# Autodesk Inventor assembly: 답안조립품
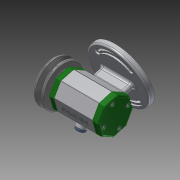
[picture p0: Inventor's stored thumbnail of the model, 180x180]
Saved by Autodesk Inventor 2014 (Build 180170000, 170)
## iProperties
Created: 2017-06
Part Number: 답안조립품
Document SubType Name: Assembly
Designer: Administrator
Author: Administrator
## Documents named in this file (13)
- C:\Users\Administrator\Desktop\470607V1004\답안조립품.iam
- C:\Users\Administrator\Desktop\470607V1004\축.ipt
- C:\Users\Administrator\Desktop\470607V1004\키 3 x 3 x 12.ipt
- C:\Users\Administrator\Desktop\470607V1004\베어링 15 x 32 x 9.ipt
- C:\Users\Administrator\Desktop\470607V1004\뒤커버.ipt
- C:\Users\Administrator\Desktop\470607V1004\본체.ipt
- C:\Users\Administrator\Desktop\470607V1004\앞커버.ipt
- C:\Users\Administrator\Desktop\470607V1004\볼트 M4 x 12.ipt
- C:\Users\Administrator\Desktop\470607V1004\V벨트풀리.ipt
- C:\Users\Administrator\Desktop\470607V1004\와셔 8x17.ipt
- C:\Users\Administrator\Desktop\470607V1004\스프링와셔 8.ipt
- C:\Users\Administrator\Desktop\470607V1004\너트 M 8.ipt
- C:\Users\Administrator\Desktop\470607V1004\고무캡.ipt
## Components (2 placed, 2 different names)
1. V벨트풀리:1 — 각도:4
2. 고무캡:1
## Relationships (1: Angle 1)
- 각도:4 [Angle]: V벨트풀리:1
